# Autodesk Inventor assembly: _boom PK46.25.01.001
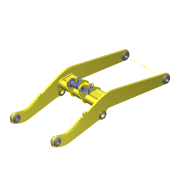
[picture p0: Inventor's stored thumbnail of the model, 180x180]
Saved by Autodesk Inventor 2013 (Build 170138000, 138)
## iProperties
Created: 2005-04
Part Number: _boom PK46.25.01.001
Document SubType Name: Assembly
Designer: salex
Manufacturer: Standard
Standards Organization: Custom
Author: salex
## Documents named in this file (13)
- C:\Product Design Suite 2013\Chassis, Front_Layout\Workspace\Assy, Chassis, Front\_boom PK46.25.01.001.iam
- C:\Product Design Suite 2013\Chassis, Front_Layout\Workspace\Assy, Chassis, Front\PK46.25.01.011.ipt
- C:\Product Design Suite 2013\Chassis, Front_Layout\Workspace\Assy, Chassis, Front\PK46.25.01.013.ipt
- C:\Product Design Suite 2013\Chassis, Front_Layout\Workspace\Assy, Chassis, Front\PK46.25.01.014.ipt
- C:\Product Design Suite 2013\Chassis, Front_Layout\Workspace\Assy, Chassis, Front\PK46.25.01.015.ipt
- C:\Product Design Suite 2013\Chassis, Front_Layout\Workspace\Assy, Chassis, Front\M10-6H.5.019(S16).ipt
- C:\Product Design Suite 2013\Chassis, Front_Layout\Workspace\Assy, Chassis, Front\10.65G.019.ipt
- C:\Product Design Suite 2013\Chassis, Front_Layout\Workspace\Assy, Chassis, Front\PK46.25.00.030.iam
- C:\Product Design Suite 2013\Chassis, Front_Layout\Workspace\Assy, Chassis, Front\PK46.25.00.008.ipt
- C:\Product Design Suite 2013\Chassis, Front_Layout\Workspace\Assy, Chassis, Front\PK46.25.00.007.ipt
- C:\Product Design Suite 2013\Chassis, Front_Layout\Workspace\Assy, Chassis, Front\PK46.25.01.011.iam
- M10-6H.5.019(S16).ipt
- 10.65G.019.ipt
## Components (38 placed, 9 different names)
1. PK46.25.01.011:9 [sub-assembly] — Insert:1, Insert:2, Insert:3, Insert:4, Insert:5, Insert:6, Insert:7, Insert:8, Insert:13, Insert:14, Insert:15, Insert:16, Mate:1, Mate:2, Mate:3, Mate:4, Mate:7, Flush:4, Flush:5, Mate:14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
2. PK46.25.00.030:1 [sub-assembly]
3. PK46.25.00.008:1
4. PK46.25.00.007:1
5. PK46.25.01.011:1 — Insert:2
6. PK46.25.01.011:2 — Insert:1
7. PK46.25.01.011:3 — Insert:7
8. PK46.25.01.011:4 — Insert:8, Flush:8
9. PK46.25.01.011:5 — Insert:6, Flush:2
10. PK46.25.01.011:6 — Insert:5
11. PK46.25.01.011:7 — Insert:4, Flush:3
12. PK46.25.01.011:8 — Insert:3
13. PK46.25.01.013:1 — Insert:9
14. PK46.25.01.013:2 — Insert:10
15. PK46.25.01.013:3 — Insert:11
16. PK46.25.01.013:4 — Insert:12
17. PK46.25.01.014:1 — Insert:9, Insert:13, Mate:3
18. PK46.25.01.014:2 — Insert:10, Insert:15, Mate:4, Insert:34, Insert:33, Insert:32, Insert:31, Insert:30, Insert:29
19. PK46.25.01.014:3 — Insert:11, Insert:14, Mate:2, Flush:6
20. PK46.25.01.014:4 — Insert:12, Insert:16, Mate:1, Insert:23, Insert:24, Insert:25, Insert:26, Insert:27, Insert:28
21. PK46.25.01.015:1 — Insert:23
22. PK46.25.01.015:2 — Insert:24
23. PK46.25.01.015:3 — Insert:25
24. PK46.25.01.015:4 — Insert:26
25. PK46.25.01.015:5 — Insert:27
26. PK46.25.01.015:6 — Insert:28
27. M10-6H.5.019(S16):1 — Insert:22
28. M10-6H.5.019(S16):2 — Insert:21
29. M10-6H.5.019(S16):3 — Insert:20
30. M10-6H.5.019(S16):4 — Insert:19
31. M10-6H.5.019(S16):5 — Insert:18
32. M10-6H.5.019(S16):6 — Insert:17
33. 10.65G.019:1 — Insert:22, Insert:34
34. 10.65G.019:2 — Insert:21, Insert:33
35. 10.65G.019:3 — Insert:20, Insert:32
36. 10.65G.019:4 — Insert:19, Insert:31
37. 10.65G.019:5 — Insert:18, Insert:30
38. 10.65G.019:6 — Insert:17, Insert:29
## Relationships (49: Insert 34, Mate 8, Flush 7)
- Insert:1: PK46.25.01.011:9 ↔ PK46.25.01.011:2
- Insert:2: PK46.25.01.011:9 ↔ PK46.25.01.011:1
- Insert:3: PK46.25.01.011:9 ↔ PK46.25.01.011:8
- Insert:4: PK46.25.01.011:9 ↔ PK46.25.01.011:7
- Insert:5: PK46.25.01.011:9 ↔ PK46.25.01.011:6
- Insert:6: PK46.25.01.011:9 ↔ PK46.25.01.011:5
- Insert:7: PK46.25.01.011:9 ↔ PK46.25.01.011:3
- Insert:8: PK46.25.01.011:9 ↔ PK46.25.01.011:4
- Insert:9: PK46.25.01.013:1 ↔ PK46.25.01.014:1
- Insert:10: PK46.25.01.013:2 ↔ PK46.25.01.014:2
- Insert:11: PK46.25.01.013:3 ↔ PK46.25.01.014:3
- Insert:12: PK46.25.01.013:4 ↔ PK46.25.01.014:4
- Insert:13: PK46.25.01.011:9 ↔ PK46.25.01.014:1
- Insert:14: PK46.25.01.011:9 ↔ PK46.25.01.014:3
- Insert:15: PK46.25.01.011:9 ↔ PK46.25.01.014:2
- Insert:16: PK46.25.01.011:9 ↔ PK46.25.01.014:4
- Mate:1: PK46.25.01.011:9 ↔ PK46.25.01.014:4
- Mate:2: PK46.25.01.011:9 ↔ PK46.25.01.014:3
- Mate:3: PK46.25.01.011:9 ↔ PK46.25.01.014:1
- Mate:4: PK46.25.01.011:9 ↔ PK46.25.01.014:2
- Insert:17: M10-6H.5.019(S16):6 ↔ 10.65G.019:6
- Insert:18: M10-6H.5.019(S16):5 ↔ 10.65G.019:5
- Insert:19: M10-6H.5.019(S16):4 ↔ 10.65G.019:4
- Insert:20: M10-6H.5.019(S16):3 ↔ 10.65G.019:3
- Insert:21: M10-6H.5.019(S16):2 ↔ 10.65G.019:2
- Insert:22: M10-6H.5.019(S16):1 ↔ 10.65G.019:1
- Insert:23: PK46.25.01.014:4 ↔ PK46.25.01.015:1
- Insert:24: PK46.25.01.014:4 ↔ PK46.25.01.015:2
- Insert:25: PK46.25.01.014:4 ↔ PK46.25.01.015:3
- Insert:26: PK46.25.01.014:4 ↔ PK46.25.01.015:4
- Insert:27: PK46.25.01.014:4 ↔ PK46.25.01.015:5
- Insert:28: PK46.25.01.014:4 ↔ PK46.25.01.015:6
- Insert:34: PK46.25.01.014:2 ↔ 10.65G.019:1
- Insert:33: PK46.25.01.014:2 ↔ 10.65G.019:2
- Insert:32: PK46.25.01.014:2 ↔ 10.65G.019:3
- Insert:31: PK46.25.01.014:2 ↔ 10.65G.019:4
- Insert:30: PK46.25.01.014:2 ↔ 10.65G.019:5
- Insert:29: PK46.25.01.014:2 ↔ 10.65G.019:6
- Flush:2: PK46.25.01.011:5
- Mate:7: PK46.25.01.011:9
- Flush:3: PK46.25.01.011:7
- Flush:4: PK46.25.01.011:9
- Flush:5: PK46.25.01.011:9
- Mate:14: PK46.25.01.011:9
- Flush:6: PK46.25.01.014:3
- Mate:17: PK46.25.01.011:9
- Flush:7: PK46.25.01.011:9
- Flush:8: PK46.25.01.011:4
- Mate:20: PK46.25.01.011:9
